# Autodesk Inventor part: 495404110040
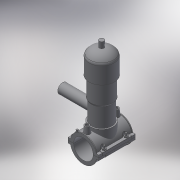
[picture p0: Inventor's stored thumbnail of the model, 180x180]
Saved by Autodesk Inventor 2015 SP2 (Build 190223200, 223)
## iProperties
Created: 2017-07
Part Number: 495404110040
Material: Generic
Description: PLASSON TAPPING VALVE 110-40
Document SubType Name: Modeling
Designer: KIM
Density: 1 g/cm^3
Appearance: Default
Author: KIM
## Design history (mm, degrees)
derived "495404-4954S4.ipt"
feature "Solid1::495404-4954S4.ipt"
feature "Solid2::495404-4954S4.ipt"
tag "TaggingFeature1"
body "Solid1"
body "Solid2"
other parameters: "d2" = 148, "d3" = 27.5, "d4" = 118, "d5" = 0, "d6" = 0.1, "d8" = 0, "d19" = 6, "d20" = 6, "d21" = 70.8, "d23" = 0, "d24" = 35.4, "d26" = 0, "d27" = 3, "d28" = 3, "d29" = 3, "d30" = 36.66667, "d31" = 6, "d32" = 0, "d33" = 0, "d34" = 0.6, "d40" = 71.5, "d47" = 114.75, "d70" = 15, "d72" = 0, "d73" = 6, "d75" = 5, "d76" = 0, "d77" = 5.5, "d78" = 85, "d79" = 15, "d80" = 47.2, "d82" = 5 deg, "d84" = 4, "d85" = 14, "d86" = 0, "d87" = 3, "d88" = 0, "d89" = 1, "d90" = 1, "d91" = 94.4, "d92" = 0, "d93" = 0.5, "d94" = 57.89474, "d96" = 141.625, "d97" = 2.36, "d98" = 0, "d120" = 140 deg, "d121" = 24.228, "d122" = 20 deg, "d123" = 275, "d124" = 82.5, "d126" = 0, "d143" = 113.3, "d145" = 21.15385, "d149" = 1.65, "d150" = 23.26923, "d153" = 118, "d154" = 0, "d156" = 68.75, "d157" = 160 deg, "d159" = 5.5, "d161" = 1.65, "d162" = 70.8, "d163" = 0, "d164" = 55, "d167" = 11, "d168" = 67.07317, "d170" = 3, "d172" = 0, "d173" = 1, "d175" = 55, "d176" = 20 deg, "d177" = 7.7, "d178" = 27.5, "d180" = 0, "d183" = 11, "d184" = 6.16, "d185" = 38.35, "d186" = 38.35, "d187" = 68.75, "d188" = 8.25, "d189" = 7.7, "d190" = 0, "d191" = 103.125, "d193" = 6.8, "d194" = 2.95, "d195" = 90 deg, "d197" = 0, "d199" = 0, "d205" = 14.64, "d206" = 81.33333, "d207" = 244, "d208" = 224.48, "d209" = 207.4, "d210" = 200.08, "d211" = 146.4, "d212" = 85.4, "d213" = 65.88, "d214" = 73.2, "d216" = 19.52, "d217" = 70.76, "d218" = 80.52, "d222" = 0, "d223" = 137.5, "d224" = 137, "d225" = 46, "d229" = 137, "d230" = 0, "B_" = 148, "H_" = 137, "L_" = 118, "d_t" = 6, "H_1" = 46, "H_2" = 244, "d148" = 1.65, "d160" = 1.65, "d169" = 3, "d192" = 6.8, "d228" = 32
